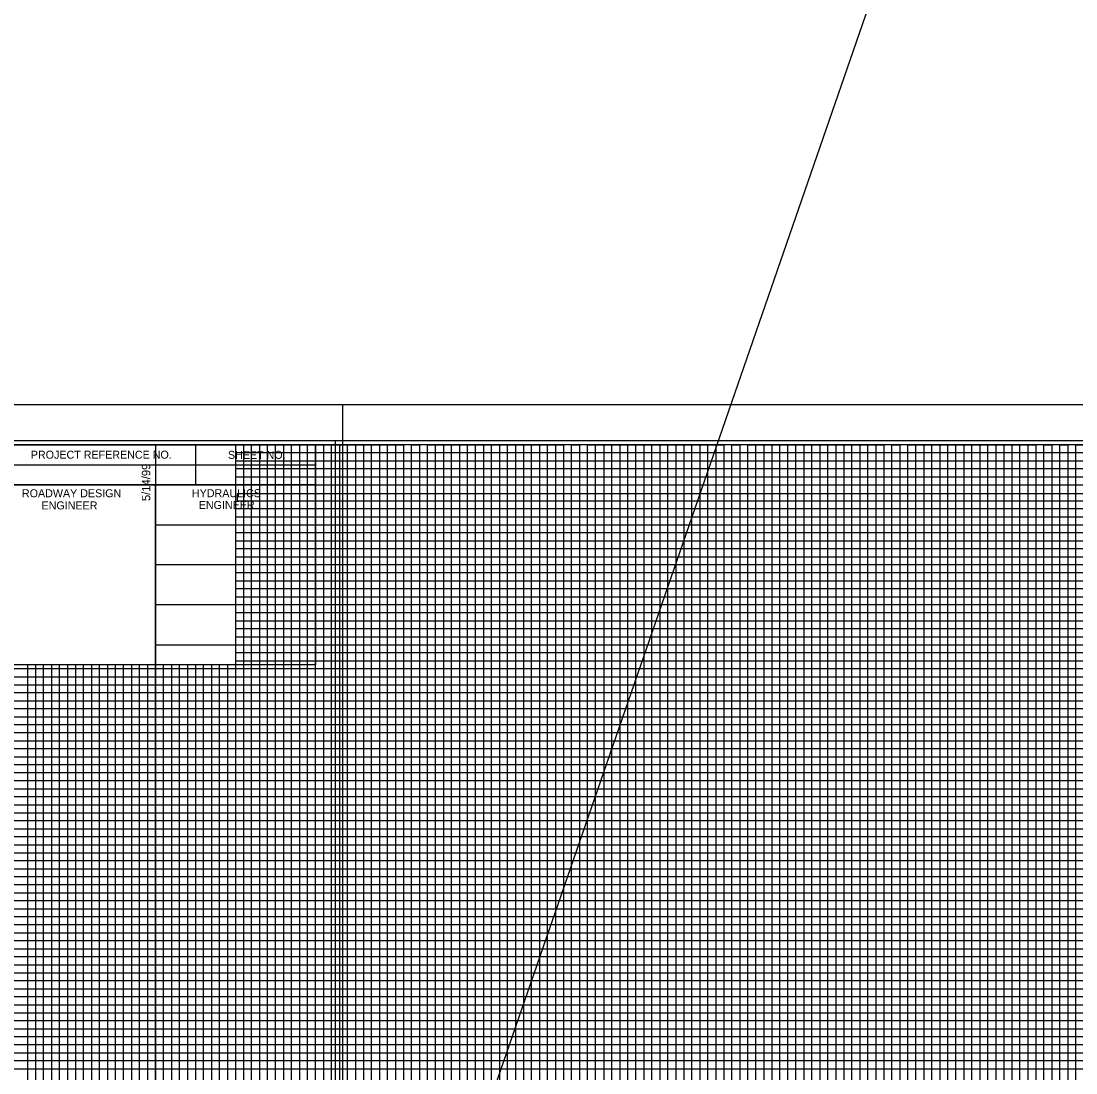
# Model space of a CAD drawing. Extents: x 2345490 to 2436403, y 465165 to 573888.
# Drawn here: x 2412161 to 2412820, y 514864 to 515521 of the extents above; entities that cross this region are included whole.
import ezdxf

# ---------------------------------------------------------------- set-up
doc = ezdxf.new("R2010")
doc.units = 0
for name, color, linetype in [('Old_Level_1', 7, 'Continuous'), ('Old_Level_18', 7, 'Continuous'), ('Old_Level_2', 7, 'Continuous'), ('Old_Level_40', 7, 'Continuous'), ('Old_Level_41', 7, 'Continuous'), ('Old_Level_42', 7, 'Continuous'), ('Old_Level_43', 7, 'Continuous'), ('Old_Level_44', 7, 'Continuous'), ('Old_Level_50', 7, 'Continuous'), ('Old_Level_51', 7, 'Continuous'), ('Old_Level_52', 7, 'Continuous'), ('Old_Level_53', 7, 'Continuous')]:
    doc.layers.add(name, color=color, linetype=linetype)

msp = doc.modelspace()

# ---------------------------------------------------------------- linework, layer by layer
at = {"layer": 'Old_Level_1'}
msp.add_line((2412357.825, 515258.76425), (2412357.825, 515258.76425), dxfattribs=at)
at = {"layer": 'Old_Level_18'}
for points in [[(2412345.325, 515256.21425), (2410845.325, 515256.21425), (2410845.325, 514206.21425), (2412345.325, 514206.21425)], [(2413745.325, 515256.21425), (2412245.325, 515256.21425), (2412245.325, 514206.21425), (2413745.325, 514206.21425)]]:
    msp.add_lwpolyline(points, close=True, dxfattribs=at)
at = {"layer": 'Old_Level_2'}
msp.add_line((2406888.2485, 498751.813), (2414623.19775, 521117.51825), dxfattribs=at)
at = {"layer": 'Old_Level_40'}
for p, q in [((2412270.325, 515256.16425), (2412270.325, 515231.16425)), ((2412145.275, 515243.66425), (2412345.325, 515243.66425)), ((2412245.325, 515231.16425), (2412245.325, 515118.71425))]:
    msp.add_line(p, q, dxfattribs=at)
for points in [[(2412145.275, 515256.21425), (2412345.325, 515256.21425), (2412345.325, 515231.16425), (2412145.275, 515231.16425)], [(2412145.275, 515231.16425), (2412245.325, 515231.16425), (2412245.325, 515118.66425), (2412145.275, 515118.66425)], [(2412245.325, 515231.16425), (2412345.325, 515231.16425), (2412345.325, 515118.66425), (2412245.325, 515118.66425)]]:
    msp.add_lwpolyline(points, close=True, dxfattribs=at)
at = {"layer": 'Old_Level_41'}
for points in [[(2412145.325, 515256.21425), (2412171.625, 515256.21425)], [(2412245.325, 515256.21425), (2412295.325, 515256.21425), (2412295.325, 514231.21425), (2412345.325, 514231.21425), (2412345.325, 515256.21425), (2412395.325, 515256.21425), (2412395.325, 514231.21425), (2412445.325, 514231.21425), (2412445.325, 515256.21425), (2412495.325, 515256.21425), (2412495.325, 514231.21425), (2412545.325, 514231.21425), (2412545.325, 515256.21425), (2412595.325, 515256.21425), (2412595.325, 514231.21425), (2412645.325, 514231.21425), (2412645.325, 515256.21425), (2412695.325, 515256.21425), (2412695.325, 514231.21425), (2412745.325, 514231.21425), (2412745.325, 515256.21425), (2412795.325, 515256.21425), (2412795.325, 514231.21425), (2412845.325, 514231.21425)], [(2412320.325, 514231.21425), (2412320.325, 515256.21425), (2412370.325, 515256.21425), (2412370.325, 514231.21425), (2412420.325, 514231.21425), (2412420.325, 515256.21425), (2412470.325, 515256.21425), (2412470.325, 514231.21425), (2412520.325, 514231.21425), (2412520.325, 515256.21425), (2412570.325, 515256.21425), (2412570.325, 514231.21425), (2412620.325, 514231.21425), (2412620.325, 515256.21425), (2412670.325, 515256.21425), (2412670.325, 514231.21425), (2412720.325, 514231.21425), (2412720.325, 515256.21425), (2412770.325, 515256.21425), (2412770.325, 514231.21425), (2412820.325, 514231.21425), (2412820.325, 515256.21425), (2412870.325, 515256.21425)], [(2412245.325, 515206.21425), (2413545.275, 515206.21425)], [(2412145.275, 515156.21425), (2410845.325, 515156.21425), (2410845.325, 515106.16425), (2412345.325, 515106.16425)], [(2413545.275, 515156.21425), (2412245.325, 515156.21425), (2412245.325, 515106.16425), (2413745.325, 515106.16425)], [(2412345.325, 515081.21425), (2410845.325, 515081.21425), (2410845.325, 515131.21425), (2412145.275, 515131.21425)], [(2413745.325, 515081.21425), (2412245.325, 515081.21425), (2412245.325, 515131.21425), (2413545.275, 515131.21425)], [(2412170.325, 515118.66425), (2412170.325, 514231.21425), (2412220.325, 514231.21425), (2412220.325, 515118.66425)], [(2412270.325, 515118.66425), (2412270.325, 514231.21425)], [(2412345.325, 515056.21425), (2410845.325, 515056.21425), (2410845.325, 515006.21425), (2412345.325, 515006.21425)], [(2413745.325, 515056.21425), (2412245.325, 515056.21425), (2412245.325, 515006.21425), (2413745.325, 515006.21425)], [(2412345.325, 514981.21425), (2410845.325, 514981.21425), (2410845.325, 515031.21425), (2412345.325, 515031.21425)], [(2413745.325, 514981.21425), (2412245.325, 514981.21425), (2412245.325, 515031.21425), (2413745.325, 515031.21425)], [(2412345.325, 514956.21425), (2410845.325, 514956.21425), (2410845.325, 514906.21425), (2412345.325, 514906.21425)], [(2413745.325, 514956.21425), (2412245.325, 514956.21425), (2412245.325, 514906.21425), (2413745.325, 514906.21425)]]:
    msp.add_lwpolyline(points, dxfattribs=at)
at = {"layer": 'Old_Level_42'}
for points in [[(2413545.275, 515181.21425), (2412245.425, 515181.21425), (2412245.425, 515231.16425), (2413545.275, 515231.16425)], [(2412195.325, 515118.66425), (2412195.325, 514231.21425), (2412245.325, 514231.21425), (2412245.325, 515118.66425)], [(2412295.325, 515118.66425), (2412295.325, 514231.21425), (2412345.325, 514231.21425)], [(2412345.325, 514881.21425), (2410845.325, 514881.21425), (2410845.325, 514931.21425), (2412345.325, 514931.21425)], [(2413745.325, 514881.21425), (2412245.325, 514881.21425), (2412245.325, 514931.21425), (2413745.325, 514931.21425)]]:
    msp.add_lwpolyline(points, dxfattribs=at)
at = {"layer": 'Old_Level_43'}
for p, q in [((2412295.325, 515076.21425), (2410895.325, 515076.21425)), ((2413695.325, 515076.21425), (2412295.325, 515076.21425)), ((2412295.325, 515076.21425), (2412295.325, 515071.21425)), ((2410895.325, 515071.21425), (2412295.325, 515071.21425)), ((2412295.325, 515071.21425), (2413695.325, 515071.21425)), ((2412295.325, 515051.21425), (2410895.325, 515051.21425)), ((2413695.325, 515051.21425), (2412295.325, 515051.21425))]:
    msp.add_line(p, q, dxfattribs=at)
for points in [[(2412300.325, 515256.21425), (2412305.325, 515256.21425), (2412310.325, 515256.21425), (2412315.325, 515256.21425), (2412325.325, 515256.21425), (2412292.275, 515256.21425), (2412297.275, 515256.21425), (2412255.325, 515256.21425), (2412260.325, 515256.21425), (2412265.325, 515256.21425), (2412275.325, 515256.21425), (2412280.325, 515256.21425), (2412285.325, 515256.21425), (2412290.325, 515256.21425), (2412300.325, 515256.21425), (2412300.325, 514231.21425)], [(2412305.325, 514231.21425), (2412305.325, 515256.21425), (2412310.325, 515256.21425), (2412310.325, 514231.21425)], [(2412315.325, 514231.21425), (2412315.325, 515256.21425), (2412325.325, 515256.21425), (2412325.325, 514231.21425)], [(2412330.325, 514231.21425), (2412330.325, 515256.21425), (2412335.325, 515256.21425), (2412335.325, 514231.21425)], [(2412340.325, 514231.21425), (2412340.325, 515256.21425), (2412350.325, 515256.21425), (2412350.325, 514231.21425)], [(2412355.325, 514231.21425), (2412355.325, 515256.21425), (2412360.325, 515256.21425), (2412360.325, 514231.21425)], [(2412365.325, 514231.21425), (2412365.325, 515256.21425), (2412375.325, 515256.21425), (2412375.325, 514231.21425)], [(2412380.325, 514231.21425), (2412380.325, 515256.21425), (2412385.325, 515256.21425), (2412385.325, 514231.21425)], [(2412390.325, 514231.21425), (2412390.325, 515256.21425), (2412400.325, 515256.21425), (2412400.325, 514231.21425)], [(2412405.325, 514231.21425), (2412405.325, 515256.21425), (2412410.325, 515256.21425), (2412410.325, 514231.21425)], [(2412415.325, 514231.21425), (2412415.325, 515256.21425), (2412425.325, 515256.21425), (2412425.325, 514231.21425)], [(2412430.325, 514231.21425), (2412430.325, 515256.21425), (2412435.325, 515256.21425), (2412435.325, 514231.21425)], [(2412440.325, 514231.21425), (2412440.325, 515256.21425), (2412450.325, 515256.21425), (2412450.325, 514231.21425)], [(2412455.325, 514231.21425), (2412455.325, 515256.21425), (2412460.325, 515256.21425), (2412460.325, 514231.21425)], [(2412465.325, 514231.21425), (2412465.325, 515256.21425), (2412475.325, 515256.21425), (2412475.325, 514231.21425)], [(2412480.325, 514231.21425), (2412480.325, 515256.21425), (2412485.325, 515256.21425), (2412485.325, 514231.21425)], [(2412490.325, 514231.21425), (2412490.325, 515256.21425), (2412500.325, 515256.21425), (2412500.325, 514231.21425)], [(2412505.325, 514231.21425), (2412505.325, 515256.21425), (2412505.325, 515256.21425), (2412510.325, 515256.21425), (2412510.325, 514231.21425)], [(2412515.325, 514231.21425), (2412515.325, 515256.21425), (2412525.325, 515256.21425), (2412525.325, 514231.21425)], [(2412530.325, 514231.21425), (2412530.325, 515256.21425), (2412535.325, 515256.21425), (2412535.325, 514231.21425)], [(2412540.325, 514231.21425), (2412540.325, 515256.21425), (2412550.325, 515256.21425), (2412550.325, 514231.21425)], [(2412555.325, 514231.21425), (2412555.325, 515256.21425), (2412560.325, 515256.21425), (2412560.325, 514231.21425)], [(2412565.325, 514231.21425), (2412565.325, 515256.21425), (2412575.325, 515256.21425), (2412575.325, 514231.21425)], [(2412580.325, 514231.21425), (2412580.325, 515256.21425), (2412585.325, 515256.21425), (2412585.325, 514231.21425)], [(2412590.325, 514231.21425), (2412590.325, 515256.21425), (2412600.325, 515256.21425), (2412600.325, 514231.21425)], [(2412605.325, 514231.21425), (2412605.325, 515256.21425), (2412610.325, 515256.21425), (2412610.325, 514231.21425)], [(2412615.325, 514231.21425), (2412615.325, 515256.21425), (2412625.325, 515256.21425), (2412625.325, 514231.21425)], [(2412630.325, 515256.21425), (2412630.325, 514231.21425), (2412635.325, 514231.21425), (2412635.325, 515256.21425)], [(2412630.325, 515255.61425), (2412630.325, 514231.21425), (2412635.325, 514231.21425), (2412635.325, 515255.61425)], [(2412640.325, 514231.21425), (2412640.325, 515256.21425), (2412650.325, 515256.21425), (2412650.325, 514231.21425)], [(2412655.325, 514231.21425), (2412655.325, 515256.21425), (2412660.325, 515256.21425), (2412660.325, 514231.21425)], [(2412665.325, 514231.21425), (2412665.325, 515256.21425), (2412675.325, 515256.21425), (2412675.325, 514231.21425)], [(2412680.325, 514231.21425), (2412680.325, 515256.21425), (2412685.325, 515256.21425), (2412685.325, 514231.21425)], [(2412690.325, 514231.21425), (2412690.325, 515256.21425), (2412700.325, 515256.21425), (2412700.325, 514231.21425)], [(2412705.325, 514231.21425), (2412705.325, 515256.21425), (2412710.325, 515256.21425), (2412710.325, 514231.21425)], [(2412715.325, 514231.21425), (2412715.325, 515256.21425), (2412725.325, 515256.21425), (2412725.325, 514231.21425)], [(2412730.325, 514231.21425), (2412730.325, 515256.21425), (2412735.325, 515256.21425), (2412735.325, 514231.21425)], [(2412740.325, 514231.21425), (2412740.325, 515256.21425), (2412750.325, 515256.21425), (2412750.325, 514231.21425)], [(2412755.325, 514231.21425), (2412755.325, 515256.21425), (2412760.325, 515256.21425), (2412760.325, 514231.21425)], [(2412765.325, 514231.21425), (2412765.325, 515256.21425), (2412775.325, 515256.21425), (2412775.325, 514231.21425)], [(2412780.325, 515256.21425), (2412780.325, 514231.21425), (2412785.325, 514231.21425), (2412785.325, 515256.21425), (2412790.325, 515256.21425), (2412790.325, 514231.21425), (2412800.325, 514231.21425), (2412800.325, 515256.21425), (2412805.325, 515256.21425), (2412805.325, 514231.21425), (2412810.325, 514231.21425), (2412810.325, 515256.21425), (2412815.325, 515256.21425), (2412815.325, 514231.21425)], [(2413545.275, 515251.21425), (2412295.325, 515251.21425), (2412295.325, 515246.21425), (2413545.275, 515246.21425)], [(2413545.275, 515241.21425), (2412295.325, 515241.21425), (2412295.325, 515236.21425), (2413545.275, 515236.21425)], [(2413545.275, 515225.46425), (2412296.325, 515225.46425), (2412296.325, 515221.21425), (2413545.275, 515221.21425)], [(2413545.275, 515216.21425), (2412295.325, 515216.21425), (2412295.325, 515211.21425), (2413545.275, 515211.21425)], [(2413545.275, 515201.21425), (2412295.325, 515201.21425), (2412295.325, 515196.21425), (2413545.275, 515196.21425)], [(2413545.275, 515191.21425), (2412295.325, 515191.21425), (2412295.325, 515186.21425), (2413545.275, 515186.21425)], [(2413545.275, 515176.21425), (2412295.325, 515176.21425), (2412295.325, 515171.21425), (2413545.275, 515171.21425)], [(2413545.275, 515166.21425), (2412295.325, 515166.21425), (2412295.325, 515161.21425), (2413545.275, 515161.21425)], [(2413545.275, 515151.21425), (2412295.325, 515151.21425), (2412295.325, 515146.21425), (2413545.275, 515146.21425)], [(2413545.275, 515141.21425), (2412295.325, 515141.21425), (2412295.325, 515136.21425), (2413545.275, 515136.21425)], [(2413545.275, 515126.21425), (2412295.325, 515126.21425), (2412295.325, 515121.21425), (2413545.275, 515121.21425)], [(2412295.325, 515116.21425), (2410895.325, 515116.21425), (2410895.325, 515116.21425), (2410895.325, 515096.21425), (2412295.325, 515096.21425)], [(2412165.325, 515118.66425), (2412165.325, 514231.21425), (2412175.325, 514231.21425), (2412175.325, 515118.66425)], [(2412180.325, 515118.66425), (2412180.325, 514231.21425), (2412185.325, 514231.21425), (2412185.325, 515118.66425)], [(2412190.325, 515118.66425), (2412190.325, 514231.21425), (2412200.325, 514231.21425), (2412200.325, 515118.66425)], [(2412205.325, 515118.66425), (2412205.325, 514231.21425), (2412210.325, 514231.21425), (2412210.325, 515118.66425)], [(2412215.325, 515118.66425), (2412215.325, 514231.21425), (2412225.325, 514231.21425), (2412225.325, 515118.66425)], [(2412230.325, 515118.66425), (2412230.325, 514231.21425)], [(2412230.325, 514231.21425), (2412235.325, 514231.21425), (2412235.325, 515118.66425)], [(2412240.325, 515118.66425), (2412240.325, 514231.21425), (2412250.325, 514231.21425), (2412250.325, 515118.66425)], [(2412255.325, 515118.66425), (2412255.325, 514231.21425), (2412260.325, 514231.21425), (2412260.325, 515118.66425)], [(2412265.325, 515118.66425), (2412265.325, 514231.21425), (2412275.325, 514231.21425), (2412275.325, 515118.66425)], [(2412280.325, 515118.66425), (2412280.325, 514231.21425), (2412285.325, 514231.21425), (2412285.325, 515118.66425)], [(2412290.325, 515118.66425), (2412290.325, 514231.21425), (2412300.325, 514231.21425)], [(2413695.325, 515116.21425), (2412295.325, 515116.21425), (2412295.325, 515116.21425), (2412295.325, 515096.21425), (2413695.325, 515096.21425)], [(2410895.325, 515111.21425), (2412295.325, 515111.21425)], [(2412295.325, 515111.21425), (2413695.325, 515111.21425)], [(2412295.325, 515101.21425), (2410895.325, 515101.21425)], [(2413695.325, 515101.21425), (2412295.325, 515101.21425)], [(2412295.325, 515091.21425), (2410895.325, 515091.21425), (2410895.325, 515086.21425), (2412295.325, 515086.21425)], [(2413695.325, 515091.21425), (2412295.325, 515091.21425), (2412295.325, 515086.21425), (2413695.325, 515086.21425)], [(2412295.325, 515066.21425), (2410895.325, 515066.21425), (2410895.325, 515061.21425), (2412295.325, 515061.21425)], [(2413695.325, 515066.21425), (2412295.325, 515066.21425), (2412295.325, 515061.21425), (2413695.325, 515061.21425)], [(2412295.325, 515046.21425), (2410895.325, 515046.21425), (2410895.325, 515041.21425), (2412295.325, 515041.21425)], [(2413695.325, 515046.21425), (2412295.325, 515046.21425), (2412295.325, 515041.21425), (2413695.325, 515041.21425)], [(2412295.325, 515036.21425), (2410895.325, 515036.21425)], [(2413695.325, 515036.21425), (2412295.325, 515036.21425)], [(2410895.325, 515026.21425), (2412295.325, 515026.21425)], [(2412295.325, 515026.21425), (2413695.325, 515026.21425)], [(2412295.325, 515021.21425), (2410895.325, 515021.21425), (2410895.325, 515016.21425), (2412295.325, 515016.21425)], [(2413695.325, 515021.21425), (2412295.325, 515021.21425), (2412295.325, 515016.21425), (2413695.325, 515016.21425)], [(2412295.325, 515011.21425), (2410895.325, 515011.21425), (2410895.325, 515001.21425), (2412295.325, 515001.21425)], [(2413695.325, 515011.21425), (2412295.325, 515011.21425), (2412295.325, 515001.21425), (2413695.325, 515001.21425)], [(2412295.325, 514996.21425), (2410895.325, 514996.21425), (2410895.325, 514991.21425), (2412295.325, 514991.21425)], [(2413695.325, 514996.21425), (2412295.325, 514996.21425), (2412295.325, 514991.21425), (2413695.325, 514991.21425)], [(2412295.325, 514986.21425), (2410895.325, 514986.21425), (2410895.325, 514976.21425), (2412295.325, 514976.21425)], [(2413695.325, 514986.21425), (2412295.325, 514986.21425), (2412295.325, 514976.21425), (2413695.325, 514976.21425)], [(2412295.325, 514971.21425), (2410895.325, 514971.21425), (2410895.325, 514966.21425), (2412295.325, 514966.21425)], [(2413695.325, 514971.21425), (2412295.325, 514971.21425), (2412295.325, 514966.21425), (2413695.325, 514966.21425)], [(2412295.325, 514961.21425), (2410895.325, 514961.21425), (2410895.325, 514951.21425), (2412295.325, 514951.21425)], [(2413695.325, 514961.21425), (2412295.325, 514961.21425), (2412295.325, 514951.21425), (2413695.325, 514951.21425)], [(2412295.325, 514946.21425), (2410895.325, 514946.21425), (2410895.325, 514941.21425), (2412295.325, 514941.21425)], [(2413695.325, 514946.21425), (2412295.325, 514946.21425), (2412295.325, 514941.21425), (2413695.325, 514941.21425)], [(2412295.325, 514936.21425), (2410895.325, 514936.21425), (2410895.325, 514926.21425), (2412295.325, 514926.21425)], [(2413695.325, 514936.21425), (2412295.325, 514936.21425), (2412295.325, 514926.21425), (2413695.325, 514926.21425)], [(2412295.325, 514921.21425), (2410895.325, 514921.21425), (2410895.325, 514916.21425), (2412295.325, 514916.21425)], [(2413695.325, 514921.21425), (2412295.325, 514921.21425), (2412295.325, 514916.21425), (2413695.325, 514916.21425)], [(2412295.325, 514911.21425), (2410895.325, 514911.21425), (2410895.325, 514901.21425), (2412295.325, 514901.21425)], [(2413695.325, 514911.21425), (2412295.325, 514911.21425), (2412295.325, 514901.21425), (2413695.325, 514901.21425)], [(2412295.325, 514896.21425), (2410895.325, 514896.21425), (2410895.325, 514891.21425), (2412295.325, 514891.21425)], [(2413695.325, 514896.21425), (2412295.325, 514896.21425), (2412295.325, 514891.21425), (2413695.325, 514891.21425)], [(2412295.325, 514886.21425), (2410895.325, 514886.21425), (2410895.325, 514876.21425), (2412295.325, 514876.21425)], [(2413695.325, 514886.21425), (2412295.325, 514886.21425), (2412295.325, 514876.21425), (2413695.325, 514876.21425)], [(2412295.325, 514871.21425), (2410895.325, 514871.21425), (2410895.325, 514866.21425), (2412295.325, 514866.21425)], [(2413695.325, 514871.21425), (2412295.325, 514871.21425), (2412295.325, 514866.21425), (2413695.325, 514866.21425)]]:
    msp.add_lwpolyline(points, dxfattribs=at)
at = {"layer": 'Old_Level_50'}
msp.add_line((2412362.325, 515281.21425), (2412362.325, 515281.21425), dxfattribs=at)
for points in [[(2412357.825, 515258.76425), (2410691.325, 515258.76425), (2410691.325, 514203.66425), (2412357.825, 514203.66425)], [(2413757.825, 515258.76425), (2412091.325, 515258.76425), (2412091.325, 514203.66425), (2413757.825, 514203.66425)]]:
    msp.add_lwpolyline(points, close=True, dxfattribs=at)
at = {"layer": 'Old_Level_51'}
for points in [[(2412362.325, 515281.21425), (2410678.325, 515281.21425), (2410678.325, 514181.21425), (2412362.325, 514181.21425)], [(2413762.325, 515281.21425), (2412078.325, 515281.21425), (2412078.325, 514181.21425), (2413762.325, 514181.21425)]]:
    msp.add_lwpolyline(points, close=True, dxfattribs=at)
at = {"layer": 'Old_Level_52'}
msp.add_line((2412357.825, 515258.76425), (2412357.825, 515258.76425), dxfattribs=at)
at = {"layer": 'Old_Level_53'}
msp.add_line((2412357.825, 515258.76425), (2412357.825, 515258.76425), dxfattribs=at)

# ---------------------------------------------------------------- texts
at = {"layer": 'Old_Level_41'}
msp.add_text('5/14/99', height=5.25, rotation=90, dxfattribs=at).set_placement((2412242.075, 515221.01425))
at = {"layer": 'Old_Level_44'}
for s, p in [('PROJECT REFERENCE NO.', (2412167.475, 515247.51425)), ('SHEET NO.', (2412290.625, 515247.41425)), ('ROADWAY DESIGN', (2412161.925, 515223.41425)), ('HYDRAULICS', (2412268.125, 515223.46425)), ('ENGINEER', (2412174.175, 515215.81425)), ('ENGINEER', (2412272.375, 515216.11425))]:
    msp.add_text(s, height=5.0001, dxfattribs=at).set_placement(p)

doc.saveas('drawing.dxf')
